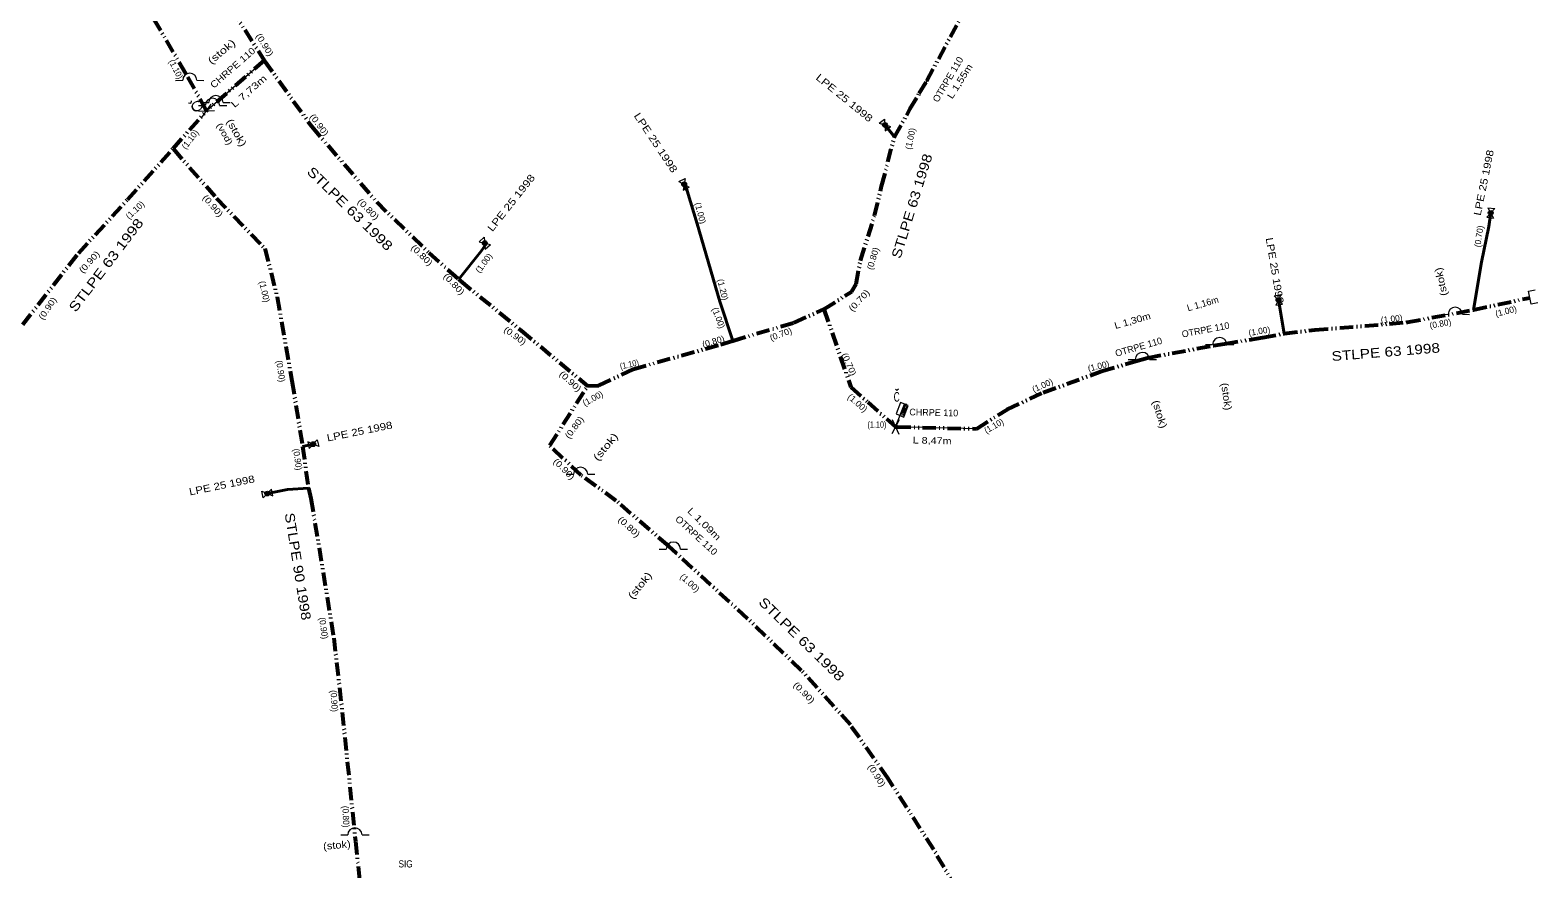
# Model space of a CAD drawing. Extents: x -648036 to -642998, y -1161549 to -1158141.
# Drawn here: x -644555.9 to -644398.6, y -1160030.1 to -1159942.6 of the extents above; entities that cross this region are included whole.
import ezdxf
from ezdxf.enums import TextEntityAlignment as Align

# ---------------------------------------------------------------- set-up
doc = ezdxf.new("R2010")
doc.units = 0
doc.header["$LTSCALE"] = 0.28
doc.header["$PDMODE"] = 32
doc.header["$PDSIZE"] = 0.14
doc.linetypes.add('DASH_DOUBLE_DOT', pattern=[9.2, 5, -1.2, 0.3, -1.2, 0.3, -1.2])
for name, color, linetype, lineweight in [('12', 7, 'DASH_DOUBLE_DOT', 40), ('14', 7, 'Continuous', 13), ('15', 7, 'Continuous', 13), ('19', 7, 'Continuous', 13), ('8', 7, 'Continuous', 53)]:
    doc.layers.add(name, color=color, linetype=linetype, lineweight=lineweight)
for name, color, linetype in [('20', 7, 'Continuous'), ('22', 7, 'Continuous'), ('24', 7, 'Continuous'), ('27', 7, 'Continuous'), ('28', 7, 'Continuous')]:
    doc.layers.add(name, color=color, linetype=linetype)

msp = doc.modelspace()

# ---------------------------------------------------------------- linework, layer by layer
at = {"layer": '12', "linetype": 'Continuous'}
for p, q in [((-644465.76, -1159953.71), (-644466.75, -1159952.46)), ((-644425.7, -1159970.72), (-644425.12, -1159974.22))]:
    msp.add_line(p, q, dxfattribs=at)
at = {"layer": '12'}
msp.add_line((-644527.51, -1159986), (-644526.39, -1159985.77), dxfattribs=at)
at = {"layer": '12', "linetype": 'Continuous'}
for points in [[(-644482.63, -1159974.98), (-644483.98, -1159970.87), (-644486.35, -1159962.78), (-644487.38, -1159959.33), (-644487.7, -1159958.65)], [(-644405.35, -1159971.75), (-644404.52, -1159966.79), (-644403.75, -1159963.07), (-644403.56, -1159961.64)], [(-644508.5, -1159964.8), (-644508.37, -1159964.95), (-644508.88, -1159965.62), (-644511.21, -1159968.57)], [(-644526.9, -1159990.37), (-644529.07, -1159990.51), (-644531.18, -1159990.93)]]:
    msp.add_lwpolyline(points, dxfattribs=at)
at = {"layer": '14'}
for p, q in [((-644537.44, -1159950.91), (-644531.51, -1159945.73)), ((-644462.39, -1159947.85), (-644463.17, -1159949.19)), ((-644432.47, -1159975.47), (-644431.32, -1159975.29)), ((-644440.59, -1159977.12), (-644439.34, -1159976.76)), ((-644457.19, -1159984.16), (-644465.66, -1159983.97)), ((-644488.51, -1159997.16), (-644489.31, -1159996.42))]:
    msp.add_line(p, q, dxfattribs=at)
at = {"layer": '15'}
for p, q in [((-644540.745, -1159947.805), (-644540.01, -1159947.804)), ((-644538.524, -1159947.804), (-644537.79, -1159947.805)), ((-644539.393, -1159950.137), (-644539.175, -1159950.171)), ((-644539.132, -1159949.954), (-644539.175, -1159950.171)), ((-644538.375, -1159950.415), (-644537.64, -1159950.414)), ((-644538.369, -1159951.026), (-644536.693, -1159950.954)), ((-644538.025, -1159950.135), (-644537.29, -1159950.134)), ((-644538.01, -1159951.678), (-644537.051, -1159950.302)), ((-644536.154, -1159950.414), (-644535.42, -1159950.415)), ((-644535.804, -1159950.134), (-644535.07, -1159950.135)), ((-644467.342, -1159952.286), (-644466.784, -1159951.844)), ((-644467.342, -1159952.286), (-644466.158, -1159952.634)), ((-644466.784, -1159951.844), (-644466.717, -1159953.075)), ((-644466.717, -1159953.075), (-644466.158, -1159952.634)), ((-644488.237, -1159958.346), (-644487.592, -1159958.042)), ((-644488.237, -1159958.346), (-644487.163, -1159958.954)), ((-644487.592, -1159958.042), (-644487.808, -1159959.257)), ((-644487.808, -1159959.257), (-644487.163, -1159958.954)), ((-644403.141, -1159961.187), (-644403.979, -1159962.092)), ((-644403.847, -1159961.094), (-644403.273, -1159962.186)), ((-644403.847, -1159961.094), (-644403.141, -1159961.187)), ((-644403.979, -1159962.092), (-644403.273, -1159962.186)), ((-644509.099, -1159964.652), (-644508.561, -1159964.186)), ((-644509.099, -1159964.652), (-644507.901, -1159964.948)), ((-644508.561, -1159964.186), (-644508.44, -1159965.413)), ((-644508.44, -1159965.413), (-644507.901, -1159964.948)), ((-644426.134, -1159970.281), (-644425.431, -1159970.165)), ((-644426.134, -1159970.281), (-644425.266, -1159971.159)), ((-644425.431, -1159970.165), (-644425.969, -1159971.274)), ((-644425.969, -1159971.274), (-644425.266, -1159971.159)), ((-644408.735, -1159972.225), (-644408, -1159972.224)), ((-644406.514, -1159972.224), (-644405.78, -1159972.225)), ((-644433.305, -1159975.385), (-644432.57, -1159975.384)), ((-644431.084, -1159975.384), (-644430.35, -1159975.385)), ((-644441.375, -1159976.945), (-644440.64, -1159976.944)), ((-644439.154, -1159976.944), (-644438.42, -1159976.945)), ((-644465.658, -1159980.029), (-644465.499, -1159980.182)), ((-644465.339, -1159980.029), (-644465.499, -1159980.182)), ((-644465.66, -1159983.97), (-644464.717, -1159981.59)), ((-644464.639, -1159981.969), (-644464.873, -1159982.56)), ((-644464.586, -1159981.642), (-644464.717, -1159981.59)), ((-644465.27, -1159983.227), (-644466.049, -1159984.712)), ((-644466.015, -1159983.21), (-644465.305, -1159984.729)), ((-644526.954, -1159985.522), (-644526.812, -1159986.22)), ((-644525.825, -1159986.017), (-644526.954, -1159985.522)), ((-644525.968, -1159985.32), (-644526.812, -1159986.22)), ((-644525.968, -1159985.32), (-644525.825, -1159986.017)), ((-644499.975, -1159988.915), (-644499.24, -1159988.914)), ((-644497.754, -1159988.914), (-644497.02, -1159988.915)), ((-644531.744, -1159990.679), (-644530.617, -1159991.181)), ((-644531.605, -1159991.378), (-644531.744, -1159990.679)), ((-644531.605, -1159991.378), (-644530.755, -1159990.482)), ((-644530.617, -1159991.181), (-644530.755, -1159990.482)), ((-644490.295, -1159996.735), (-644489.56, -1159996.734)), ((-644488.074, -1159996.734), (-644487.34, -1159996.735)), ((-644523.525, -1160026.555), (-644522.79, -1160026.554)), ((-644521.304, -1160026.554), (-644520.57, -1160026.555))]:
    msp.add_line(p, q, dxfattribs=at)
msp.add_lwpolyline([(-644398.643, -1159971.031), (-644399.332, -1159971.18), (-644399.628, -1159969.8), (-644398.939, -1159969.652)], dxfattribs=at)
for points in [[(-644465.592, -1159982.621), (-644464.785, -1159982.941), (-644464.314, -1159981.751), (-644465.12, -1159981.431)], [(-644465.022, -1159982.662), (-644464.826, -1159982.741), (-644464.473, -1159981.85), (-644464.669, -1159981.772)]]:
    msp.add_lwpolyline(points, close=True, dxfattribs=at)
for centre in [(-644539.2674, -1159947.8046), (-644536.5474, -1159950.1346), (-644536.8974, -1159950.4146), (-644407.2574, -1159972.2246), (-644431.8274, -1159975.3846), (-644439.8974, -1159976.9446), (-644498.4974, -1159988.9146), (-644488.8174, -1159996.7346), (-644522.0474, -1160026.5546)]:
    msp.add_arc(centre, 0.7431, 1.2748, 179.83951, dxfattribs=at)
msp.add_point((-644464.586, -1159981.642), dxfattribs=at)
at = {"layer": '19'}
for centre, radius in [((-644466.75, -1159952.46), 0.25), ((-644466.75, -1159952.46), 0.17), ((-644466.75, -1159952.46), 0.09), ((-644487.7, -1159958.65), 0.25), ((-644487.7, -1159958.65), 0.17), ((-644487.7, -1159958.65), 0.09), ((-644403.56, -1159961.64), 0.25), ((-644403.56, -1159961.64), 0.17), ((-644403.56, -1159961.64), 0.09), ((-644508.5, -1159964.8), 0.25), ((-644508.5, -1159964.8), 0.17), ((-644508.5, -1159964.8), 0.09), ((-644425.7, -1159970.72), 0.25), ((-644425.7, -1159970.72), 0.17), ((-644425.7, -1159970.72), 0.09), ((-644526.39, -1159985.77), 0.25), ((-644526.39, -1159985.77), 0.17), ((-644526.39, -1159985.77), 0.09), ((-644531.18, -1159990.93), 0.25), ((-644531.18, -1159990.93), 0.17), ((-644531.18, -1159990.93), 0.09)]:
    msp.add_circle(centre, radius, dxfattribs=at)
at = {"layer": '8', "linetype": 'DASH_DOUBLE_DOT'}
msp.add_line((-644541.02, -1159954.93), (-644537.53, -1159950.99), dxfattribs=at)
for points in [[(-644555.146, -1159904.577), (-644549.63, -1159915.13), (-644541.05, -1159930.36), (-644534.94, -1159940.34), (-644531.51, -1159945.73)], [(-644537.53, -1159950.99), (-644539.67, -1159947.1), (-644546.9, -1159934.75), (-644549.81, -1159929.51), (-644552.28, -1159925.35)], [(-644465.76, -1159953.71), (-644464.14, -1159950.83), (-644463.17, -1159949.19), (-644462.39, -1159947.85), (-644456.94, -1159937.79), (-644456.54, -1159936.66)], [(-644531.51, -1159945.73), (-644537.44, -1159950.91), (-644537.53, -1159950.99)], [(-644531.51, -1159945.73), (-644526.58, -1159952.6), (-644519.77, -1159960.5), (-644514.32, -1159965.81), (-644511.21, -1159968.57)], [(-644473.12, -1159971.69), (-644470.2, -1159969.83), (-644469.74, -1159969.08), (-644469.3, -1159966.59), (-644467.83, -1159961.9), (-644467.1, -1159958.84), (-644465.76, -1159953.71)], [(-644556.7, -1159973.3), (-644550.89, -1159965.84), (-644545.76, -1159960.25), (-644541.02, -1159954.93)], [(-644541.02, -1159954.93), (-644536.49, -1159960.09), (-644531.43, -1159965.35), (-644530.15, -1159970.45), (-644528.62, -1159979.18), (-644527.51, -1159986), (-644526.9, -1159990.37)], [(-644511.21, -1159968.57), (-644511.02, -1159968.74), (-644504.7, -1159973.91), (-644497.77, -1159979.7)], [(-644425.12, -1159974.22), (-644421.9, -1159973.85), (-644412.26, -1159973.05), (-644405.35, -1159971.75), (-644399.48, -1159970.49)], [(-644482.63, -1159974.98), (-644476.26, -1159973.1), (-644473.12, -1159971.69)], [(-644473.12, -1159971.69), (-644470.31, -1159979.82), (-644468.53, -1159981.4), (-644465.66, -1159983.97), (-644465.456, -1159983.975)], [(-644465.456, -1159983.975), (-644457.19, -1159984.16), (-644454.01, -1159982.14), (-644450.24, -1159980.39), (-644444.16, -1159978.16), (-644440.59, -1159977.12), (-644439.34, -1159976.76), (-644432.47, -1159975.47), (-644431.32, -1159975.29), (-644427.34, -1159974.65), (-644425.12, -1159974.22)], [(-644497.77, -1159979.7), (-644496.6, -1159979.65), (-644493, -1159977.93), (-644483.87, -1159975.37), (-644482.63, -1159974.98)], [(-644444.91, -1160040.31), (-644452.39, -1160043.05), (-644452.87, -1160043.14), (-644454.99, -1160039.37), (-644459.28, -1160032.19), (-644461.66, -1160028.08), (-644466.41, -1160020.66), (-644470.35, -1160015.08), (-644475.45, -1160009.38), (-644481.06, -1160003.99), (-644488.51, -1159997.16), (-644489.31, -1159996.42), (-644494.78, -1159991.67), (-644498.45, -1159989.02), (-644501.7, -1159985.93), (-644497.77, -1159979.7)], [(-644526.9, -1159990.37), (-644526.63, -1159991.44), (-644524.25, -1160005.98), (-644523.37, -1160013.75), (-644521.99, -1160027.22), (-644521.39, -1160032.82), (-644521.27, -1160033.93), (-644520.82, -1160038.37)]]:
    msp.add_lwpolyline(points, dxfattribs=at)

# ---------------------------------------------------------------- texts
at = {"layer": '15', "width": 1.35}
msp.add_text('C', height=1, rotation=34.95, dxfattribs=at).set_placement((-644538.2514, -1159950.9325), align=Align.CENTER)
at = {"layer": '15'}
for s, height, width, p in [('C', 1, 0.65, (-644465.528, -1159981.335)), ('SIG', 0.75, 0.85, (-644516.7575, -1160029.947))]:
    msp.add_text(s, height=height, dxfattribs=dict(at, width=width)).set_placement(p, align=Align.CENTER)
at = {"layer": '20'}
for s, rotation, width, p in [('STLPE 63 1998', 72.766, 1.2, (-644463.4606, -1159961.0716)), ('STLPE 63 1998', 315.7, 1.25, (-644522.9177, -1159961.5615)), ('STLPE 63 1998', 52.712, 1.25, (-644547.6097, -1159967.3884)), ('STLPE 63 1998', 4.584, 1.2, (-644414.468, -1159976.6514)), ('STLPE 90 1998', 279.03, 1.2, (-644528.4837, -1159998.6155)), ('STLPE 63 1998', 315.7, 1.25, (-644475.7977, -1160006.4815))]:
    msp.add_text(s, height=1, rotation=rotation, dxfattribs=dict(at, width=width)).set_placement(p, align=Align.CENTER)
at = {"layer": '22'}
for rotation, width, p in [(320.856, 1.25, (-644471.2237, -1159949.9259)), (303.668, 1.25, (-644490.974, -1159954.5186)), (78.495, 1.2, (-644403.917, -1159958.5593)), (51.566, 1.25, (-644505.4478, -1159960.8201)), (279.603, 1.2, (-644426.4515, -1159967.7159)), (11.459, 1.2, (-644521.4805, -1159984.8069)), (11.459, 1.2, (-644535.8505, -1159990.4369))]:
    msp.add_text('LPE 25 1998', height=0.75, rotation=rotation, dxfattribs=dict(at, width=width)).set_placement(p, align=Align.CENTER)
at = {"layer": '24'}
for s, rotation, width, p in [('CHRPE 110 ', 41.253, 1.15, (-644534.4483, -1159946.6581)), ('OTRPE 110', 59.588, 1.05, (-644459.8772, -1159947.8867)), ('L 1,55m', 57.869, 1.2, (-644458.6508, -1159948.0902)), ('L 7,73m', 41.253, 1.35, (-644532.8853, -1159949.2061)), ('L 1,30m', 16.043, 1.15, (-644440.8347, -1159973.2242)), ('L 8,47m', 358.672, 1.2, (-644461.8401, -1159985.7452)), ('OTRPE 110', 317.419, 1.1, (-644486.6543, -1159995.5523)), ('L 1,09m', 315.7, 1.3, (-644485.8479, -1159994.349))]:
    msp.add_text(s, height=0.7, rotation=rotation, dxfattribs=dict(at, width=width)).set_placement(p, align=Align.CENTER)
for s, rotation, p in [('L 1,16m', 16.043, (-644433.5042, -1159971.4461)), ('OTRPE 110', 10.886, (-644433.2381, -1159974.1756)), ('OTRPE 110', 16.043, (-644440.1922, -1159975.9643)), ('CHRPE 110 ', 358.672, (-644461.5361, -1159982.823))]:
    msp.add_text(s, height=0.7, rotation=rotation, dxfattribs=at).set_placement(p, align=Align.CENTER)
at = {"layer": '27'}
for s, rotation, width, p in [('(0.90)', 301.949, 1.15, (-644531.7286, -1159944.263)), ('(1.10)', 297.365, 0.95, (-644541.0035, -1159946.7856)), ('(vod)', 299.084, 1.25, (-644535.9105, -1159953.551)), ('(0.90)', 307.105, 1.15, (-644526.0248, -1159952.6429)), ('(0.90)', 310.543, 1.2, (-644537.1079, -1159961.1117)), ('(0.80)', 315.127, 1.2, (-644520.8773, -1159961.4826)), ('(0.80)', 315.7, 1.2, (-644515.291, -1159966.2861)), ('(0.90)', 48.701, 1.2, (-644549.511, -1159966.974)), ('(0.80)', 73.339, 1.05, (-644467.6973, -1159966.4932)), ('(0.80)', 313.408, 1.2, (-644511.942, -1159969.2852)), ('(0.70)', 46.983, 1.2, (-644469.2082, -1159970.9997)), ('(0.90)', 55.577, 1.15, (-644553.843, -1159971.7832)), ('(0.90)', 324.294, 1.15, (-644505.5257, -1159974.7155)), ('(0.80)', 16.616, 1.05, (-644484.5644, -1159975.3676)), ('(0.70)', 20.626, 1.05, (-644477.503, -1159974.591)), ('(1.10)', 12.032, 0.85, (-644493.3477, -1159977.7652)), ('(0.70)', 293.927, 1.1, (-644470.7922, -1159977.5672)), ('(0.90)', 317.419, 1.2, (-644499.7874, -1159979.4511)), ('(1.00)', 318.565, 1.05, (-644469.8196, -1159981.7101)), ('(0.80)', 53.285, 1.15, (-644498.8977, -1159984.2233)), ('(1.10)', 29.794, 0.95, (-644455.228, -1159984.1569)), ('(0.90)', 315.127, 1.2, (-644500.4548, -1159988.5941)), ('(0.80)', 317.419, 1.2, (-644493.6599, -1159994.6397)), ('(1.00)', 317.992, 1.05, (-644487.3165, -1160000.4846)), ('(0.90)', 314.554, 1.2, (-644475.4184, -1160011.9235)), ('(0.90)', 302.522, 1.15, (-644467.8742, -1160020.5173))]:
    msp.add_text(s, height=0.65, rotation=rotation, dxfattribs=dict(at, width=width)).set_placement(p, align=Align.CENTER)
for s, rotation, p in [('(1.10)', 52.139, (-644538.9826, -1159954.1705)), ('(1.00)', 77.922, (-644463.79, -1159953.965)), ('(1.10)', 42.972, (-644544.765, -1159961.5784)), ('(1.00)', 284.76, (-644486.3209, -1159961.7417)), ('(0.70)', 81.36, (-644404.4713, -1159964.1353)), ('(1.00)', 53.858, (-644508.3382, -1159967.0627)), ('(1.00)', 283.041, (-644531.7903, -1159969.9312)), ('(1.20)', 283.614, (-644483.9775, -1159969.7255)), ('(1.00)', 14.324, (-644401.8904, -1159972.2104)), ('(1.00)', 290.49, (-644484.416, -1159972.7077)), ('(1.00)', 6.303, (-644413.8592, -1159973.0146)), ('(0.80)', 10.313, (-644408.7517, -1159973.5216)), ('(1.00)', 9.74, (-644427.64, -1159974.2989)), ('(0.90)', 278.458, (-644530.0983, -1159978.2042)), ('(1.00)', 13.751, (-644444.3943, -1159977.9409)), ('(1.00)', 24.064, (-644450.18, -1159979.939)), ('(1.00)', 29.221, (-644497.0672, -1159981.2829)), ('(0.90)', 277.885, (-644528.3382, -1159987.4104)), ('(0.90)', 277.885, (-644525.6282, -1160005.0204)), ('(0.90)', 273.301, (-644524.5249, -1160012.5943)), ('(0.80)', 272.728, (-644523.3054, -1160024.664))]:
    msp.add_text(s, height=0.65, rotation=rotation, dxfattribs=at).set_placement(p, align=Align.CENTER)
at = {"layer": '27', "width": 0.8}
msp.add_text('(1.10)', height=0.65, dxfattribs=at).set_placement((-644467.59, -1159984.05), align=Align.CENTER)
at = {"layer": '28'}
for rotation, width, p in [(40.107, 1.35, (-644535.7211, -1159945.0961)), (299.657, 1.25, (-644534.7142, -1159953.4479)), (102.559, 1.2, (-644408.3791, -1159968.7505)), (277.885, 1.15, (-644431.4933, -1159980.8516)), (287.052, 1.2, (-644438.4438, -1159982.755)), (50.42, 1.35, (-644495.6127, -1159986.2909)), (50.993, 1.3, (-644492.0309, -1160000.7555)), (5.157, 1.15, (-644523.8952, -1160027.985))]:
    msp.add_text('(stok)', height=0.75, rotation=rotation, dxfattribs=dict(at, width=width)).set_placement(p, align=Align.CENTER)

doc.saveas('drawing.dxf')
